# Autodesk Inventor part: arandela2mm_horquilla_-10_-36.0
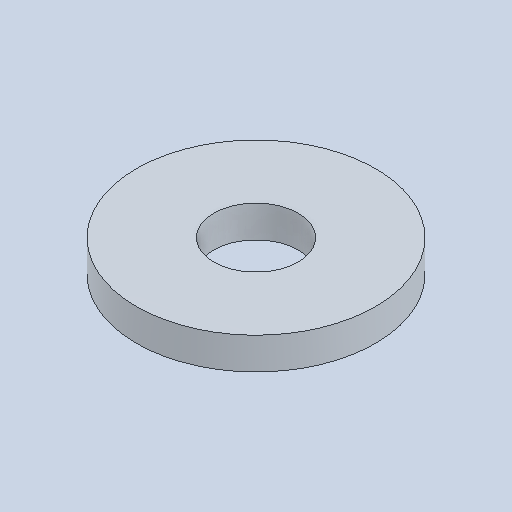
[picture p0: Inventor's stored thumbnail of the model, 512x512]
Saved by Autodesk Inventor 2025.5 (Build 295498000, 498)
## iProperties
Created: 2026-10
Part Number: arandela2mm_horquilla_-10_-36.0
Material: Genérico
Document SubType Name: Modeling
Designer: Luis M
Density: 1 g/cm^3
Appearance: Valor por defecto
Author: Luis M
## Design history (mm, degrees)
feature "Base1"
node "Sólido1"
